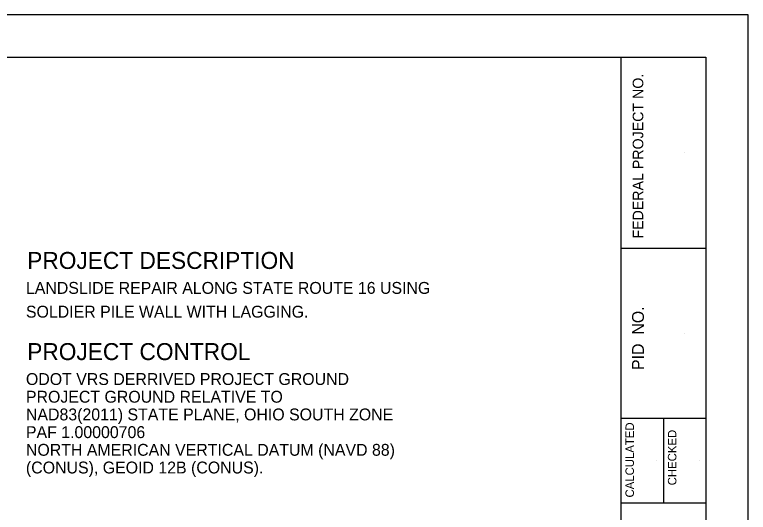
# Model space of a CAD drawing. Extents: x 0 to 34, y 0 to 22.
# Drawn here: x 25.36 to 34, y 16.14 to 22 of the extents above; entities that cross this region are included whole.
import ezdxf

# ---------------------------------------------------------------- set-up
doc = ezdxf.new("R2010")
doc.units = 0
for name, color, linetype in [('SH_Border', 7, 'Continuous'), ('SH_Cut_Line', 7, 'Continuous'), ('SH_Data', 7, 'Continuous'), ('SH_Text', 7, 'Continuous')]:
    doc.layers.add(name, color=color, linetype=linetype)

msp = doc.modelspace()

# ---------------------------------------------------------------- linework, layer by layer
at = {"layer": 'SH_Border'}
for p, q in [((32.5, 0.5), (32.5, 21.5)), ((32.5, 19.25), (33.5, 19.25)), ((32.5, 17.25), (33.5, 17.25)), ((32.5, 17.25), (33.5, 17.25)), ((33, 17.25), (33, 16.25)), ((32.5, 16.25), (33.5, 16.25))]:
    msp.add_line(p, q, dxfattribs=at)
msp.add_lwpolyline([(2, 21.5), (33.5, 21.5), (33.5, 0.5), (2, 0.5)], close=True, dxfattribs=at)
at = {"layer": 'SH_Cut_Line'}
msp.add_lwpolyline([(0, 0), (34, 0), (34, 22), (0, 22)], close=True, dxfattribs=at)
at = {"layer": 'SH_Data'}
for p, q in [((33.25, 20.375), (33.25, 20.375)), ((33.25, 18.25), (33.25, 18.25)), ((32.92, 16.7536), (32.92, 16.7536)), ((33.42, 16.7536), (33.42, 16.7536))]:
    msp.add_line(p, q, dxfattribs=at)

# ---------------------------------------------------------------- texts
for s, height, p in [('FEDERAL PROJECT NO.', 0.125, (32.7625, 19.3638)), ('PID  NO.', 0.14, (32.77, 17.8159)), ('CALCULATED', 0.1, (32.6525, 16.3146)), ('CHECKED', 0.1, (33.1525, 16.4579))]:
    msp.add_text(s, height=height, rotation=90, dxfattribs=at).set_placement(p)
at = {"layer": 'SH_Text'}
for s, height, p in [('PROJECT DESCRIPTION', 0.2, (25.5034, 19.006)), ('LANDSLIDE REPAIR ALONG STATE ROUTE 16 USING', 0.14, (25.4882, 18.7127)), ('SOLDIER PILE WALL WITH LAGGING.', 0.14, (25.4882, 18.4326)), ('PROJECT CONTROL', 0.2, (25.5034, 17.9326)), ('ODOT VRS DERRIVED PROJECT GROUND ', 0.14, (25.4882, 17.6393)), ('PROJECT GROUND RELATIVE TO ', 0.14, (25.4882, 17.431)), ('NAD83(2011) STATE PLANE, OHIO SOUTH ZONE', 0.14, (25.4882, 17.2226)), ('PAF 1.00000706', 0.14, (25.4882, 17.0143)), ('NORTH AMERICAN VERTICAL DATUM (NAVD 88)', 0.14, (25.4882, 16.8059)), ('(CONUS), GEOID 12B (CONUS).', 0.14, (25.4882, 16.5976))]:
    msp.add_text(s, height=height, dxfattribs=at).set_placement(p)

doc.saveas('drawing.dxf')
